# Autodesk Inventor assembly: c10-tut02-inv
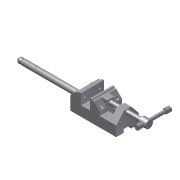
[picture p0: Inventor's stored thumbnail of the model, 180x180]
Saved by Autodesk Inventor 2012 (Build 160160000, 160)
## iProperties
Created: 2009-05
Part Number: c10-tut02-inv
Document SubType Name: Assembly
Designer: Sham
Author: Sham
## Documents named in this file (9)
- C:\Users\CadCim\Documents\SAILESH\NEW Menuscript\c10\tUT02\c10-tut02-inv.iam
- C:\Users\CadCim\Documents\SAILESH\NEW Menuscript\c10\tUT02\Base.ipt
- C:\Users\CadCim\Documents\SAILESH\NEW Menuscript\c10\tUT02\Safety Handle.ipt
- C:\Users\CadCim\Documents\SAILESH\NEW Menuscript\c10\tUT02\Jaw Face.ipt
- C:\Users\CadCim\Documents\SAILESH\NEW Menuscript\c10\tUT02\Movable Jaw.ipt
- C:\Users\CadCim\Documents\SAILESH\NEW Menuscript\c10\tUT02\Cap Screw.ipt
- C:\Users\CadCim\Documents\SAILESH\NEW Menuscript\c10\tUT02\Clamp Screw Handle.ipt
- C:\Users\CadCim\Documents\SAILESH\NEW Menuscript\c10\tUT02\Clamp Screw.ipt
- C:\Users\CadCim\Documents\SAILESH\NEW Menuscript\c10\tUT02\Handle Stop.ipt
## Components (13 placed, 8 different names)
1. Base:1 — Mate:2, Mate:3, Mate:7, Insert:10, Insert:11, Insert:12, Insert:13
2. Safety Handle:1
3. Jaw Face:1 — Insert:8, Insert:9, Mate:7
4. Jaw Face:2 — Insert:10, Insert:11
5. Movable Jaw:1 — Mate:2, Mate:3, Insert:2, Insert:3, Insert:4, Insert:8, Insert:9
6. Cap Screw:1 — Insert:2
7. Cap Screw:2 — Insert:3
8. Cap Screw:3 — Insert:13
9. Cap Screw:4 — Insert:12
10. Clamp Screw:1 — Insert:4, Mate:6, Rotation/Translation:2
11. Clamp Screw Handle:1 — Mate:6, Insert:5, Insert:6, Rotation/Translation:2
12. Handle Stop:1 — Insert:6, Mate:8
13. Handle Stop:2 — Insert:5
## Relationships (17: Insert 11, Mate 5, RelateRotateTranslate 1)
- Mate:2: Base:1 ↔ Movable Jaw:1
- Mate:3: Base:1 ↔ Movable Jaw:1
- Insert:2: Movable Jaw:1 ↔ Cap Screw:1
- Insert:3: Movable Jaw:1 ↔ Cap Screw:2
- Insert:4: Movable Jaw:1 ↔ Clamp Screw:1
- Mate:6: Clamp Screw:1 ↔ Clamp Screw Handle:1
- Insert:5: Clamp Screw Handle:1 ↔ Handle Stop:2
- Insert:6: Clamp Screw Handle:1 ↔ Handle Stop:1
- Insert:8: Jaw Face:1 ↔ Movable Jaw:1
- Insert:9: Jaw Face:1 ↔ Movable Jaw:1
- Mate:7: Base:1 ↔ Jaw Face:1
- Rotation/Translation:2 [RelateRotateTranslate]: Clamp Screw:1 ↔ Clamp Screw Handle:1
- Mate:8: Handle Stop:1
- Insert:10: Base:1 ↔ Jaw Face:2
- Insert:11: Base:1 ↔ Jaw Face:2
- Insert:12: Base:1 ↔ Cap Screw:4
- Insert:13: Base:1 ↔ Cap Screw:3
